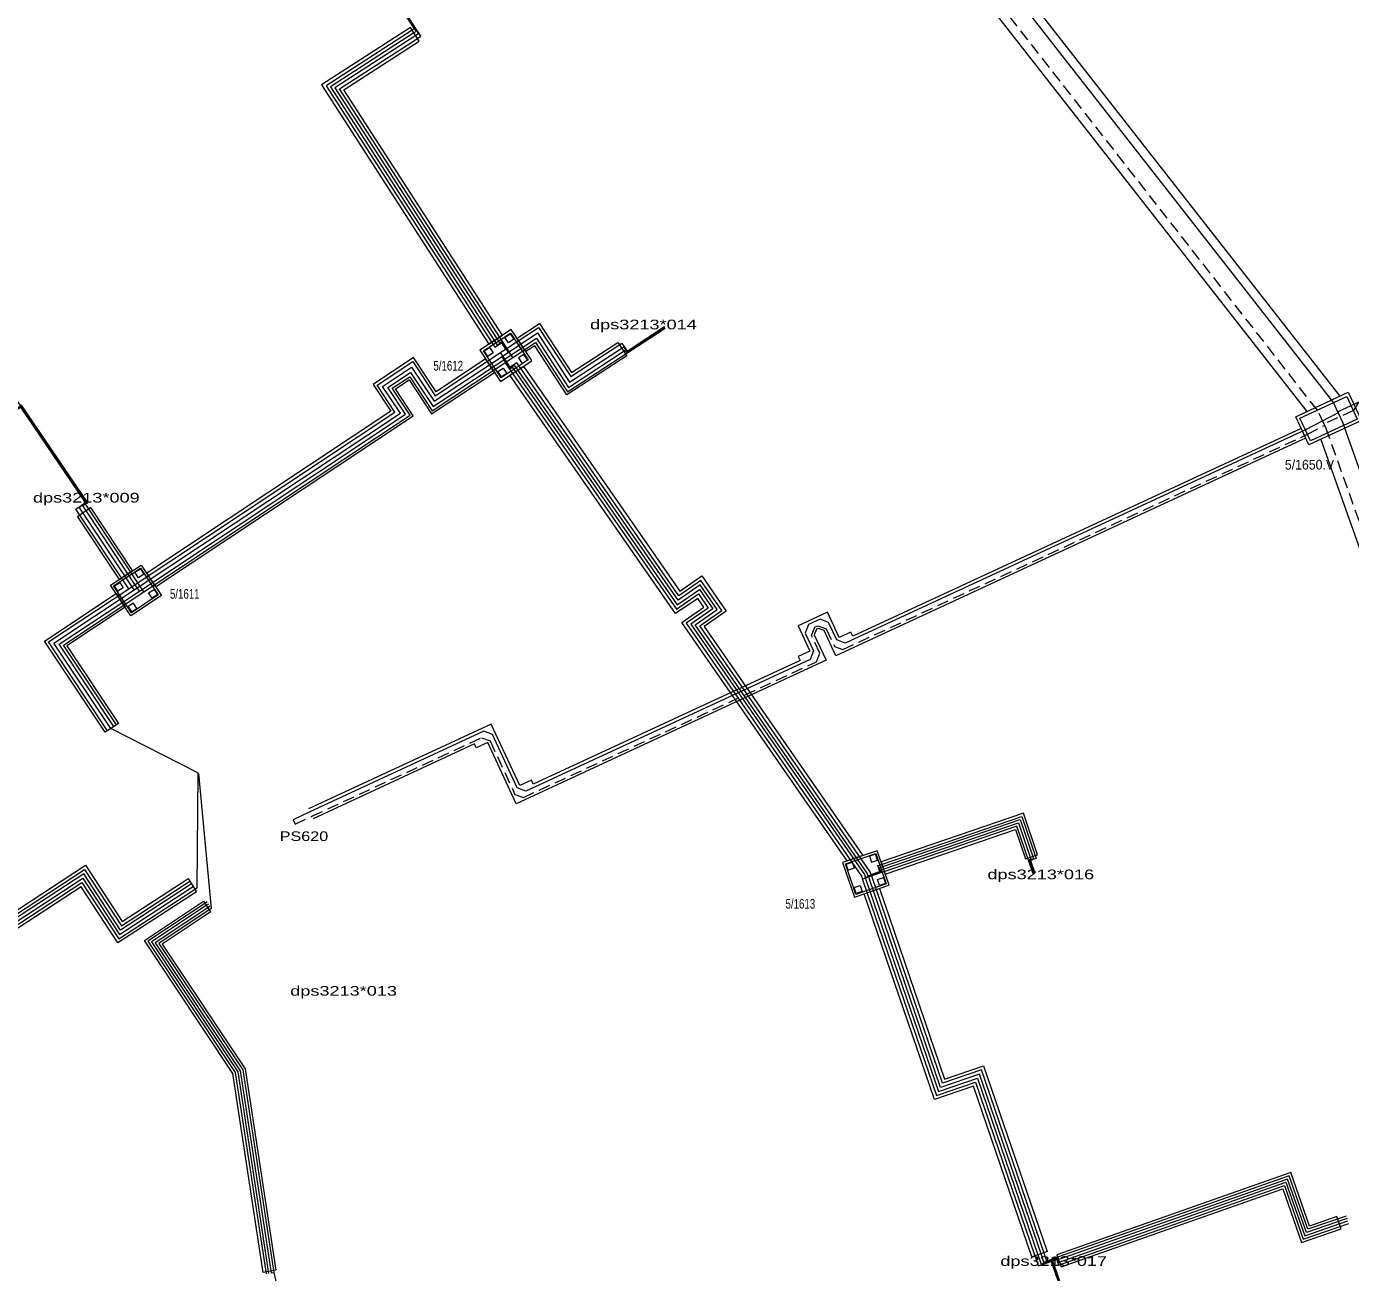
# Model space of a CAD drawing. Extents: x -473467 to -473049, y -1106745 to -1106181.
# Drawn here: x -473368.1 to -473244.9, y -1106580.3 to -1106464.4 of the extents above; entities that cross this region are included whole.
import ezdxf
from ezdxf.enums import TextEntityAlignment as Align

# ---------------------------------------------------------------- set-up
doc = ezdxf.new("R2010")
doc.units = 0
doc.header["$LTSCALE"] = 0.36
doc.linetypes.add('MEDIUM_DASHED', pattern=[4.5, 3, -1.5])
for name, color, linetype, lineweight in [('1', 7, 'MEDIUM_DASHED', 13), ('11', 7, 'Continuous', 13), ('14', 7, 'Continuous', 13), ('15', 7, 'Continuous', 13), ('17', 7, 'Continuous', 13), ('4', 7, 'Continuous', 13), ('7', 7, 'Continuous', 13)]:
    doc.layers.add(name, color=color, linetype=linetype, lineweight=lineweight)
for name, color, linetype in [('16', 7, 'Continuous'), ('19', 7, 'Continuous'), ('6', 7, 'Continuous'), ('9', 7, 'Continuous')]:
    doc.layers.add(name, color=color, linetype=linetype)

msp = doc.modelspace()

# ---------------------------------------------------------------- linework, layer by layer
at = {"layer": '1', "linetype": 'Continuous'}
msp.add_line((-473246.061, -1106500.236), (-473246.013, -1106500.34), dxfattribs=at)
at = {"layer": '1'}
msp.add_line((-473247.258, -1106501.495), (-473247.32, -1106501.369), dxfattribs=at)
at = {"layer": '1', "linetype": 'Continuous'}
for points in [[(-473352.415, -1106364.072), (-473351.401, -1106365.177), (-473320.246, -1106405.022), (-473320.796, -1106409.514), (-473325.208, -1106412.964), (-473325.757, -1106417.456), (-473324.773, -1106418.715), (-473320.281, -1106419.265), (-473315.869, -1106415.815), (-473311.377, -1106416.365), (-473246.451, -1106499.393), (-473246.061, -1106500.236)], [(-473246.061, -1106500.236), (-473244.807, -1106499.655), (-473238.151, -1106496.572)], [(-473246.013, -1106500.34), (-473249.064, -1106501.926), (-473291.881, -1106521.757), (-473292.677, -1106521.465), (-473293.433, -1106519.834), (-473294.23, -1106519.54), (-473295.321, -1106520.042), (-473295.614, -1106520.837), (-473294.856, -1106522.474), (-473295.148, -1106523.27), (-473321.618, -1106535.53), (-473322.414, -1106535.238), (-473324.723, -1106530.254), (-473325.52, -1106529.962), (-473341.711, -1106537.461), (-473343.286, -1106538.191)], [(-473246.013, -1106500.34), (-473245.619, -1106501.193), (-473182.812, -1106677.763), (-473178.72, -1106679.719), (-473101.034, -1106652.497), (-473096.956, -1106654.459), (-473096.08, -1106656.96), (-473095.369, -1106658.988)]]:
    msp.add_lwpolyline(points, dxfattribs=at)
at = {"layer": '1'}
for points in [[(-473247.32, -1106501.369), (-473247.945, -1106500.085), (-473311.652, -1106418.606), (-473316.144, -1106418.057), (-473320.555, -1106421.506), (-473325.047, -1106420.956), (-473327.999, -1106417.182), (-473327.449, -1106412.69), (-473323.038, -1106409.24), (-473322.488, -1106404.748), (-473352.595, -1106366.242), (-473353.967, -1106364.728)], [(-473237.921, -1106497.017), (-473238.243, -1106497.166), (-473239.22, -1106497.122), (-473244.159, -1106499.41), (-473244.597, -1106500.109), (-473247.32, -1106501.37)], [(-473343.286, -1106538.191), (-473343.096, -1106538.599), (-473341.522, -1106537.87), (-473325.739, -1106530.559), (-473324.942, -1106530.851), (-473322.634, -1106535.836), (-473321.837, -1106536.128), (-473294.551, -1106523.489), (-473294.259, -1106522.693), (-473295.016, -1106521.058), (-473294.723, -1106520.262), (-473294.45, -1106520.137), (-473293.653, -1106520.43), (-473292.897, -1106522.062), (-473292.1, -1106522.355), (-473248.866, -1106502.33), (-473247.258, -1106501.495)], [(-473097.014, -1106659.141), (-473097.592, -1106657.49), (-473097.935, -1106656.511), (-473102.013, -1106654.549), (-473179.701, -1106681.772), (-473183.794, -1106679.815), (-473247.114, -1106501.803), (-473247.258, -1106501.495)]]:
    msp.add_lwpolyline(points, dxfattribs=at)
at = {"layer": '11'}
for p, q in [((-473334.93, -1106460.095), (-473332.017, -1106464.606)), ((-473358.581, -1106516.712), (-473363.509, -1106509.289)), ((-473352.141, -1106533.836), (-473360.249, -1106529.711)), ((-473352.141, -1106533.836), (-473352.225, -1106544.524)), ((-473352.076, -1106533.881), (-473350.888, -1106546.448))]:
    msp.add_line(p, q, dxfattribs=at)
for points in [[(-473362.859, -1106508.966), (-473362.452, -1106508.691), (-473368.583, -1106499.672), (-473368.855, -1106499.858), (-473369.127, -1106499.459), (-473391.519, -1106466.551), (-473391.231, -1106466.356), (-473397.396, -1106457.287), (-473397.406, -1106457.272), (-473397.679, -1106457.458), (-473397.908, -1106457.12), (-473397.988, -1106457.003), (-473420.06, -1106424.535), (-473420.167, -1106424.378), (-473419.892, -1106424.19), (-473420.43, -1106423.291)], [(-473359.708, -1106529.352), (-473359.708, -1106529.352), (-473364.632, -1106521.935), (-473357.166, -1106516.999), (-473362.207, -1106509.406), (-473362.511, -1106508.948), (-473362.584, -1106508.841), (-473362.382, -1106508.704), (-473368.57, -1106499.603), (-473368.652, -1106499.659), (-473391.278, -1106466.448), (-473391.162, -1106466.369), (-473397.365, -1106457.244), (-473397.393, -1106457.203), (-473397.434, -1106457.231), (-473397.509, -1106457.281), (-473397.615, -1106457.124), (-473397.71, -1106456.985), (-473397.79, -1106456.868), (-473419.862, -1106424.4), (-473419.754, -1106424.327), (-473420.387, -1106423.265)], [(-473360.467, -1106426.653), (-473359.564, -1106427.79), (-473359.759, -1106427.945), (-473352.055, -1106437.656), (-473350.071, -1106436.375), (-473334.9, -1106459.871), (-473334.832, -1106459.976), (-473334.87, -1106460), (-473334.828, -1106460.066), (-473331.606, -1106465.058), (-473331.869, -1106465.228), (-473339.383, -1106470.08), (-473324.055, -1106493.811), (-473324.055, -1106493.811), (-473323.849, -1106493.678), (-473323.021, -1106494.959)], [(-473322.813, -1106495.182), (-473323.102, -1106494.742), (-473338.968, -1106470.169), (-473331.706, -1106465.48), (-473331.401, -1106465.284), (-473334.774, -1106460.038), (-473334.818, -1106459.969), (-473334.579, -1106459.815), (-473334.648, -1106459.708), (-473349.982, -1106435.96), (-473351.989, -1106437.257), (-473359.714, -1106427.522), (-473360.429, -1106426.621)], [(-473334.915, -1106460.026), (-473334.888, -1106460.068), (-473331.811, -1106464.833)], [(-473332.017, -1106464.606), (-473332.194, -1106464.725), (-473340.212, -1106469.901), (-473324.563, -1106494.139), (-473324.508, -1106494.223), (-473323.878, -1106493.816), (-473323.496, -1106494.408)], [(-473331.811, -1106464.833), (-473332.032, -1106464.976), (-473339.798, -1106469.991), (-473324.311, -1106493.976), (-473324.284, -1106494.018), (-473323.863, -1106493.747), (-473323.253, -1106494.692)], [(-473357.582, -1106516.915), (-473332.807, -1106500.467), (-473334.461, -1106497.964), (-473332.342, -1106496.564), (-473330.247, -1106499.735), (-473320.635, -1106493.382), (-473317.646, -1106497.96), (-473312.359, -1106494.508), (-473312.222, -1106494.718), (-473308.688, -1106492.41)], [(-473357.166, -1106516.999), (-473332.391, -1106500.551), (-473334.044, -1106498.049), (-473332.427, -1106496.981), (-473330.332, -1106500.151), (-473320.722, -1106493.8), (-473317.733, -1106498.376), (-473308.639, -1106492.438)], [(-473323.697, -1106494.541), (-473320.428, -1106492.381), (-473317.436, -1106496.962), (-473312.67, -1106493.849)], [(-473312.67, -1106493.849), (-473312.193, -1106494.579), (-473308.723, -1106492.302)], [(-473312.509, -1106494.187), (-473312.208, -1106494.649), (-473308.694, -1106492.354)], [(-473323.459, -1106494.828), (-473320.534, -1106492.896), (-473317.544, -1106497.475), (-473312.509, -1106494.187)], [(-473358.581, -1106516.712), (-473358.173, -1106516.441), (-473333.806, -1106500.264), (-473335.46, -1106497.76), (-473332.138, -1106495.565), (-473330.043, -1106498.735), (-473323.697, -1106494.541)], [(-473358.067, -1106516.816), (-473357.968, -1106516.75), (-473333.292, -1106500.368), (-473334.946, -1106497.865), (-473332.243, -1106496.079), (-473330.148, -1106499.249), (-473323.459, -1106494.828)], [(-473289.499, -1106543.226), (-473289.567, -1106543.028), (-473305.433, -1106520.143), (-473303.379, -1106518.719), (-473305.316, -1106515.925), (-473307.371, -1106517.35), (-473322.421, -1106495.709), (-473322.448, -1106495.667), (-473323.075, -1106496.082), (-473323.974, -1106494.724)], [(-473289.77, -1106543.361), (-473289.837, -1106543.165), (-473305.851, -1106520.068), (-473303.796, -1106518.643), (-473305.392, -1106516.342), (-473307.446, -1106517.767), (-473322.667, -1106495.88), (-473323.077, -1106496.165), (-473323.835, -1106495.076)], [(-473323.676, -1106495.392), (-473323.09, -1106496.235), (-473322.885, -1106496.092), (-473307.522, -1106518.184), (-473305.467, -1106516.76), (-473304.214, -1106518.568), (-473306.268, -1106519.992), (-473290.107, -1106543.301), (-473289.957, -1106543.741), (-473283.203, -1106563.48), (-473279.578, -1106562.24), (-473273.953, -1106578.676), (-473273.685, -1106579.458), (-473273.652, -1106579.553), (-473272.704, -1106579.219)], [(-473323.548, -1106495.664), (-473307.597, -1106518.601), (-473305.543, -1106517.177), (-473304.631, -1106518.492), (-473306.686, -1106519.917), (-473290.378, -1106543.438), (-473290.241, -1106543.839), (-473283.39, -1106563.861), (-473279.765, -1106562.621), (-473274.237, -1106578.773), (-473273.966, -1106579.562), (-473273.918, -1106579.704), (-473272.731, -1106579.298)], [(-473363.509, -1106509.289), (-473362.591, -1106508.665), (-473368.609, -1106499.811), (-473369.023, -1106500.092), (-473369.196, -1106500.21), (-473369.51, -1106499.749)], [(-473363.175, -1106509.122), (-473362.521, -1106508.678), (-473368.596, -1106499.742), (-473369.009, -1106500.023), (-473369.026, -1106500.034), (-473369.054, -1106499.993), (-473369.325, -1106499.594)], [(-473358.067, -1106516.816), (-473362.748, -1106509.765), (-473363.053, -1106509.307), (-473363.175, -1106509.122)], [(-473357.776, -1106516.623), (-473362.457, -1106509.572), (-473362.761, -1106509.113), (-473362.859, -1106508.966)], [(-473360.557, -1106529.916), (-473360.557, -1106529.916), (-473366.047, -1106521.648), (-473358.581, -1106516.712)], [(-473360.249, -1106529.711), (-473360.249, -1106529.711), (-473365.533, -1106521.752), (-473358.067, -1106516.816)], [(-473359.958, -1106529.518), (-473359.958, -1106529.518), (-473365.048, -1106521.851), (-473357.582, -1106516.915), (-473357.776, -1106516.623)], [(-473289.478, -1106543.286), (-473288.66, -1106543.006), (-473288.845, -1106542.467), (-473288.514, -1106542.353), (-473275.456, -1106537.883), (-473274.15, -1106541.712), (-473274.117, -1106541.806)], [(-473274.391, -1106543.233), (-473275.905, -1106538.798), (-473288.281, -1106543.034), (-473288.517, -1106543.115), (-473290.281, -1106543.719)], [(-473290.014, -1106543.575), (-473288.533, -1106543.068), (-473288.595, -1106542.888), (-473288.358, -1106542.807), (-473275.755, -1106538.493), (-473274.603, -1106541.869), (-473274.783, -1106541.93), (-473274.349, -1106543.202)], [(-473289.746, -1106543.43), (-473288.597, -1106543.037), (-473288.72, -1106542.677), (-473288.436, -1106542.58), (-473275.605, -1106538.188), (-473274.374, -1106541.796), (-473274.358, -1106541.844)], [(-473274.117, -1106541.806), (-473274.657, -1106541.99), (-473274.254, -1106543.173)], [(-473382.655, -1106555.901), (-473362.678, -1106542.825), (-473359.255, -1106548.057), (-473353.404, -1106544.25), (-473352.894, -1106543.918)], [(-473274.358, -1106541.844), (-473274.718, -1106541.967), (-473274.297, -1106543.201)], [(-473394.778, -1106566.95), (-473394.634, -1106566.821), (-473384.904, -1106558.068), (-473384.603, -1106557.871), (-473383.234, -1106559.963), (-473380.481, -1106558.161), (-473381.85, -1106556.069), (-473362.847, -1106543.63), (-473359.424, -1106548.861), (-473352.834, -1106544.573), (-473352.573, -1106544.403)], [(-473394.522, -1106567.111), (-473394.456, -1106567.052), (-473394.422, -1106567.021), (-473384.726, -1106558.299), (-473384.687, -1106558.274), (-473383.318, -1106560.365), (-473380.078, -1106558.245), (-473381.447, -1106556.153), (-473362.931, -1106544.032), (-473359.509, -1106549.263), (-473352.549, -1106544.734), (-473352.225, -1106544.524)], [(-473352.731, -1106544.161), (-473353.119, -1106544.411), (-473359.34, -1106548.459), (-473362.763, -1106543.227), (-473382.253, -1106555.985)], [(-473273.385, -1106579.406), (-473273.402, -1106579.359), (-473273.628, -1106578.697), (-473279.392, -1106561.859), (-473283.017, -1106563.099), (-473289.673, -1106543.644), (-473289.77, -1106543.361)], [(-473273.119, -1106579.259), (-473273.333, -1106578.633), (-473279.205, -1106561.478), (-473282.83, -1106562.718), (-473289.389, -1106543.547), (-473289.499, -1106543.226)], [(-473351.287, -1106545.848), (-473351.489, -1106545.983), (-473356.785, -1106549.503), (-473348.658, -1106561.727), (-473345.79, -1106580.462)], [(-473351.154, -1106546.048), (-473351.357, -1106546.183), (-473356.452, -1106549.57), (-473348.429, -1106561.639), (-473345.554, -1106580.415)], [(-473351.021, -1106546.248), (-473351.224, -1106546.383), (-473356.119, -1106549.637), (-473348.2, -1106561.55), (-473345.319, -1106580.369), (-473345.132, -1106580.332), (-473345.132, -1106580.334)], [(-473350.888, -1106546.448), (-473351.091, -1106546.582), (-473355.786, -1106549.704), (-473347.971, -1106561.461), (-473345.083, -1106580.322)], [(-473245.262, -1106575.077), (-473248.821, -1106576.307), (-473250.576, -1106571.323), (-473272.65, -1106579.094)], [(-473272.731, -1106579.298), (-473272.205, -1106579.118), (-473272.027, -1106579.638), (-473251.016, -1106572.241), (-473249.263, -1106577.221), (-473245.026, -1106575.758)], [(-473272.704, -1106579.219), (-473272.182, -1106579.035), (-473272.055, -1106579.394), (-473250.869, -1106571.935), (-473249.115, -1106576.917), (-473245.105, -1106575.531)], [(-473245.183, -1106575.304), (-473248.968, -1106576.612), (-473250.723, -1106571.629), (-473272.088, -1106579.151), (-473272.151, -1106578.972), (-473272.681, -1106579.158)], [(-473273.385, -1106579.406), (-473272.681, -1106579.158), (-473272.486, -1106579.711)], [(-473273.119, -1106579.259), (-473272.65, -1106579.094), (-473272.44, -1106579.69)], [(-473272.737, -1106579.3), (-473267.635, -1106593.795), (-473268.732, -1106594.181), (-473268.389, -1106595.156), (-473260.379, -1106617.917)], [(-473272.712, -1106579.222), (-473267.571, -1106593.826), (-473268.489, -1106594.148), (-473268.451, -1106594.254), (-473260.444, -1106617.011), (-473260.623, -1106617.074), (-473260.332, -1106617.899)], [(-473272.486, -1106579.711), (-473267.506, -1106593.856), (-473268.246, -1106594.116), (-473268.225, -1106594.174), (-473260.217, -1106616.932), (-473260.2, -1106616.979), (-473260.559, -1106617.105), (-473260.284, -1106617.886)], [(-473272.44, -1106579.69), (-473267.442, -1106593.886), (-473268.003, -1106594.083), (-473259.991, -1106616.851), (-473259.958, -1106616.946), (-473260.495, -1106617.135), (-473260.238, -1106617.866)], [(-473345.083, -1106580.322), (-473344.751, -1106581.695), (-473353.512, -1106583.702), (-473353.003, -1106585.919), (-473352.215, -1106585.742), (-473353.003, -1106585.919), (-473345.776, -1106617.503), (-473343.338, -1106616.944), (-473342.732, -1106619.598), (-473345.169, -1106620.157), (-473341.9, -1106634.458), (-473340.976, -1106634.245), (-473341.9, -1106634.458), (-473341.795, -1106634.904), (-473338.37, -1106649.379)]]:
    msp.add_lwpolyline(points, dxfattribs=at)
at = {"layer": '14'}
for points in [[(-473325.556, -1106494.56), (-473323.053, -1106492.906), (-473321.397, -1106495.411), (-473323.902, -1106497.063), (-473325.556, -1106494.56)], [(-473359.98, -1106516.426), (-473357.477, -1106514.771), (-473355.823, -1106517.274), (-473358.325, -1106518.928)], [(-473291.877, -1106542.299), (-473289.039, -1106541.328), (-473288.067, -1106544.167), (-473290.906, -1106545.138)]]:
    msp.add_lwpolyline(points, close=True, dxfattribs=at)
at = {"layer": '15'}
for points in [[(-473323.568, -1106493.306), (-473323.067, -1106492.975), (-473322.736, -1106493.476), (-473323.237, -1106493.807)], [(-473325.486, -1106494.574), (-473324.986, -1106494.243), (-473324.655, -1106494.744), (-473325.156, -1106495.075)], [(-473321.467, -1106495.397), (-473321.797, -1106494.896), (-473322.298, -1106495.227), (-473321.967, -1106495.728)], [(-473324.218, -1106496.493), (-473323.718, -1106496.162), (-473323.387, -1106496.663), (-473323.887, -1106496.993)], [(-473357.491, -1106514.841), (-473357.16, -1106515.341), (-473357.661, -1106515.672), (-473357.992, -1106515.172)], [(-473359.91, -1106516.44), (-473359.41, -1106516.109), (-473359.079, -1106516.61), (-473359.579, -1106516.94)], [(-473356.723, -1106517.09), (-473356.223, -1106516.759), (-473355.892, -1106517.26), (-473356.392, -1106517.591), (-473356.723, -1106517.09)], [(-473358.311, -1106518.859), (-473357.81, -1106518.528), (-473358.141, -1106518.028), (-473358.642, -1106518.359)], [(-473289.07, -1106541.392), (-473289.637, -1106541.586), (-473289.443, -1106542.154), (-473288.875, -1106541.959)], [(-473291.814, -1106542.33), (-473291.246, -1106542.136), (-473291.052, -1106542.704), (-473291.619, -1106542.898)], [(-473288.325, -1106543.568), (-473288.131, -1106544.136), (-473288.699, -1106544.33), (-473288.893, -1106543.762)], [(-473291.069, -1106544.507), (-473290.501, -1106544.312), (-473290.307, -1106544.88), (-473290.875, -1106545.074)]]:
    msp.add_lwpolyline(points, close=True, dxfattribs=at)
at = {"layer": '17'}
for points in [[(-473332.355, -1106464.475), (-473340.623, -1106469.813), (-473325.051, -1106493.927), (-473323.801, -1106493.101), (-473323.824, -1106493.064), (-473338.549, -1106470.259), (-473331.542, -1106465.735)], [(-473322.437, -1106493.385), (-473320.35, -1106492.006), (-473317.358, -1106496.588), (-473313.046, -1106493.772), (-473312.228, -1106495.024), (-473317.792, -1106498.658), (-473320.78, -1106494.082), (-473321.613, -1106494.632), (-473321.613, -1106494.632)], [(-473321.051, -1106495.482), (-473321.189, -1106495.273), (-473322.017, -1106494.02), (-473322.982, -1106492.56), (-473325.902, -1106494.489), (-473323.972, -1106497.409)], [(-473325.357, -1106495.314), (-473329.967, -1106498.361), (-473332.062, -1106495.191), (-473335.834, -1106497.684), (-473334.179, -1106500.188), (-473356.88, -1106515.258), (-473356.902, -1106515.273), (-473356.079, -1106516.519), (-473332.109, -1106500.608), (-473333.762, -1106498.107), (-473332.485, -1106497.263), (-473330.39, -1106500.433), (-473324.532, -1106496.563)], [(-473291.716, -1106542.033), (-473307.102, -1106519.841), (-473305.048, -1106518.417), (-473305.618, -1106517.594), (-473307.672, -1106519.018), (-473323.099, -1106496.833), (-473321.847, -1106496.007), (-473321.593, -1106496.373), (-473307.296, -1106516.932), (-473305.241, -1106515.507), (-473302.961, -1106518.795), (-473305.016, -1106520.219), (-473290.24, -1106541.528)], [(-473362.111, -1106509.152), (-473363.349, -1106510), (-473359.471, -1106515.84), (-473358.218, -1106515.016)], [(-473360.266, -1106516.364), (-473357.42, -1106514.49), (-473355.541, -1106517.331), (-473358.382, -1106519.21)], [(-473360.774, -1106530.06), (-473360.774, -1106530.06), (-473366.406, -1106521.577), (-473359.743, -1106517.154), (-473358.915, -1106518.405), (-473364.328, -1106521.998), (-473359.524, -1106529.23)], [(-473288.169, -1106543.25), (-473276.054, -1106539.103), (-473275.121, -1106541.838), (-473273.985, -1106541.451), (-473275.306, -1106537.578), (-473288.558, -1106542.116)], [(-473287.813, -1106544.291), (-473288.914, -1106541.074), (-473292.131, -1106542.175), (-473291.03, -1106545.392), (-473289.422, -1106544.841), (-473288.003, -1106544.356)], [(-473346.052, -1106580.324), (-473346.052, -1106580.324), (-473346.052, -1106580.324), (-473346.052, -1106580.324), (-473346.052, -1106580.324), (-473348.888, -1106561.816), (-473357.117, -1106549.436), (-473351.62, -1106545.781), (-473350.957, -1106546.778), (-473351.458, -1106547.111), (-473355.458, -1106549.77), (-473347.745, -1106561.374), (-473344.874, -1106580.115), (-473344.874, -1106580.115), (-473344.874, -1106580.115)], [(-473271.806, -1106579.815), (-473251.163, -1106572.547), (-473249.41, -1106577.526), (-473245.74, -1106576.258), (-473246.132, -1106575.124), (-473248.674, -1106576.002), (-473250.429, -1106571.017), (-473272.199, -1106578.681), (-473272.199, -1106578.681), (-473272.199, -1106578.681)]]:
    msp.add_lwpolyline(points, close=True, dxfattribs=at)
for points in [[(-473394.522, -1106567.111), (-473395.081, -1106566.049), (-473385.437, -1106557.375), (-473384.351, -1106556.664), (-473382.982, -1106558.755), (-473381.688, -1106557.909), (-473383.058, -1106555.817), (-473362.594, -1106542.422), (-473359.171, -1106547.655), (-473353.689, -1106544.088), (-473353.049, -1106543.672), (-473352.256, -1106544.891), (-473359.593, -1106549.665), (-473363.015, -1106544.435), (-473381.045, -1106556.237), (-473379.676, -1106558.329), (-473383.402, -1106560.768), (-473384.771, -1106558.676), (-473394.246, -1106567.253), (-473394.382, -1106567.377)], [(-473273.669, -1106578.578), (-473274.52, -1106578.87), (-473279.952, -1106563.002), (-473283.577, -1106564.242), (-473290.132, -1106545.084), (-473288.711, -1106544.598)], [(-473288.711, -1106544.598), (-473282.643, -1106562.337), (-473279.018, -1106561.097), (-473273.101, -1106578.384), (-473273.669, -1106578.578)]]:
    msp.add_lwpolyline(points, dxfattribs=at)
at = {"layer": '4'}
msp.add_lwpolyline([(-473249.565, -1106500.835), (-473245.21, -1106498.818), (-473244.244, -1106500.905), (-473248.599, -1106502.923)], close=True, dxfattribs=at)
at = {"layer": '7'}
for p, q in [((-473309.106, -1106417.891), (-473245.856, -1106498.783)), ((-473311.706, -1106419.924), (-473248.928, -1106500.211))]:
    msp.add_line(p, q, dxfattribs=at)
for points in [[(-473249.964, -1106500.689), (-473249.691, -1106500.563), (-473249.692, -1106500.563), (-473245.064, -1106498.42), (-473243.846, -1106501.052), (-473248.746, -1106503.322), (-473249.965, -1106500.69)], [(-473249.461, -1106501.78), (-473291.19, -1106521.107), (-473291.358, -1106520.744), (-473292.447, -1106521.248), (-473293.539, -1106518.892), (-473296.265, -1106520.146), (-473295.17, -1106522.509), (-473296.259, -1106523.013), (-473296.091, -1106523.376), (-473320.927, -1106534.88), (-473321.095, -1106534.517), (-473322.184, -1106535.021), (-473324.829, -1106529.311), (-473341.837, -1106537.189)], [(-473249.04, -1106502.686), (-473292.766, -1106522.938), (-473293.858, -1106520.58), (-473294.39, -1106520.384), (-473294.573, -1106520.468), (-473294.769, -1106520.998), (-473293.675, -1106523.359), (-473322.503, -1106536.711), (-473325.148, -1106531.001), (-473326.237, -1106531.506), (-473326.405, -1106531.143), (-473341.417, -1106538.096)], [(-473247.638, -1106502.809), (-473184.069, -1106681.541), (-473180.872, -1106683.069), (-473102.347, -1106655.553), (-473098.524, -1106657.393), (-473098.392, -1106657.77)]]:
    msp.add_lwpolyline(points, dxfattribs=at)

# ---------------------------------------------------------------- texts
at = {"layer": '16', "width": 0.75}
for s, p in [('5/1612', (-473330.22, -1106496.396)), ('5/1611', (-473354.742, -1106517.627)), ('5/1613', (-473297.446, -1106546.466))]:
    msp.add_text(s, height=0.9, dxfattribs=at).set_placement(p)
at = {"layer": '19', "width": 1.4}
for s, p in [('dps3213*014', (-473310.671, -1106492.558)), ('dps3213*009', (-473362.521, -1106508.678)), ('dps3213*016', (-473273.688, -1106543.73)), ('dps3213*013', (-473338.577, -1106554.568)), ('dps3213*017', (-473272.486, -1106579.711))]:
    msp.add_text(s, height=0.9, dxfattribs=at).set_placement(p, align=Align.CENTER)
at = {"layer": '6', "width": 0.95}
msp.add_text('5/1650.V', height=0.9, dxfattribs=at).set_placement((-473250.968, -1106505.604))
at = {"layer": '9', "width": 1.25}
msp.add_text('PS620', height=0.9, dxfattribs=at).set_placement((-473342.267, -1106540.176), align=Align.CENTER)

doc.saveas('drawing.dxf')
